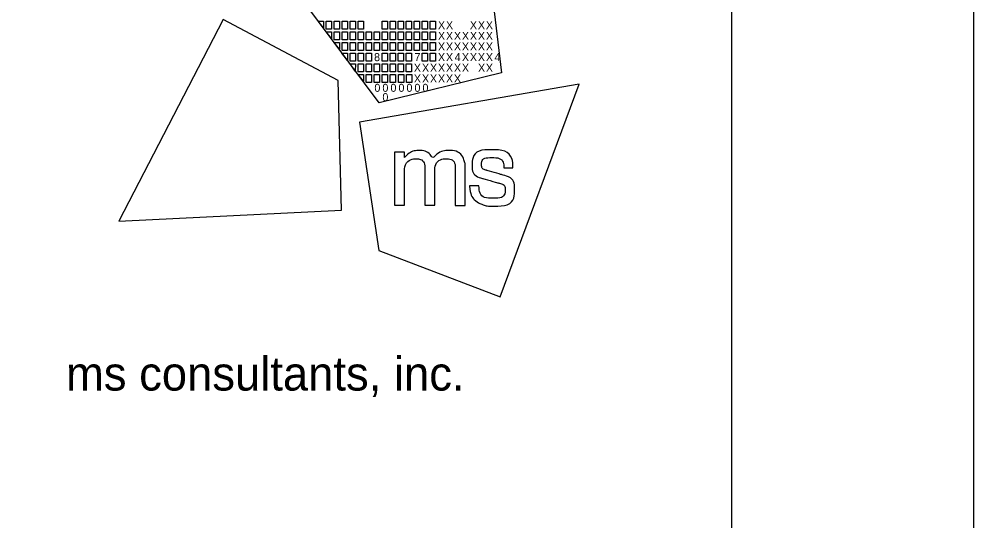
# Model space of a CAD drawing. Extents: x -18.6 to 78.7, y 0 to 36.9.
# Drawn here: x 32.03 to 34, y 2.68 to 3.716 of the extents above; entities that cross this region are included whole.
import ezdxf

# ---------------------------------------------------------------- set-up
doc = ezdxf.new("R2010")
doc.units = 0
for name, color, linetype in [('SH_Border', 7, 'Continuous'), ('SH_Cut_Line', 7, 'Continuous'), ('SH_Data', 7, 'Continuous')]:
    doc.layers.add(name, color=color, linetype=linetype)

msp = doc.modelspace()

# ---------------------------------------------------------------- linework, layer by layer
at = {"layer": 'SH_Border'}
for p, q in [((32.9688, 4.0861), (33.0253, 3.6052)), ((32.773, 3.543), (32.6175, 3.7519)), ((33.0253, 3.6052), (32.773, 3.543))]:
    msp.add_line(p, q, dxfattribs=at)
for points in [[(1.5, 21.5), (33.5, 21.5), (33.5, 0.5), (1.5, 0.5)], [(32.6471, 3.7117), (32.6581, 3.7117), (32.6581, 3.698)], [(32.6637, 3.7117), (32.6747, 3.7117), (32.6747, 3.6952), (32.6637, 3.6952)], [(32.6802, 3.7117), (32.6912, 3.7117), (32.6912, 3.6952), (32.6802, 3.6952)], [(32.6967, 3.7117), (32.7077, 3.7117), (32.7077, 3.6952), (32.6967, 3.6952)], [(32.7132, 3.7117), (32.7242, 3.7117), (32.7242, 3.6952), (32.7132, 3.6952)], [(32.7297, 3.7117), (32.7407, 3.7117), (32.7407, 3.6952), (32.7297, 3.6952)], [(32.7793, 3.7117), (32.7903, 3.7117), (32.7903, 3.6952), (32.7793, 3.6952)], [(32.7958, 3.7117), (32.8068, 3.7117), (32.8068, 3.6952), (32.7958, 3.6952)], [(32.8123, 3.7117), (32.8233, 3.7117), (32.8233, 3.6952), (32.8123, 3.6952)], [(32.8288, 3.7117), (32.8398, 3.7117), (32.8398, 3.6952), (32.8288, 3.6952)], [(32.8453, 3.7117), (32.8563, 3.7117), (32.8563, 3.6952), (32.8453, 3.6952)], [(32.8618, 3.7117), (32.8728, 3.7117), (32.8728, 3.6952), (32.8618, 3.6952)], [(32.8783, 3.7117), (32.8893, 3.7117), (32.8893, 3.6952), (32.8783, 3.6952)], [(32.6637, 3.6897), (32.6747, 3.6897), (32.6747, 3.676)], [(32.6747, 3.6897), (32.6747, 3.6897), (32.6747, 3.6897)], [(32.6802, 3.6897), (32.6912, 3.6897), (32.6912, 3.6732), (32.6802, 3.6732)], [(32.6967, 3.6897), (32.7077, 3.6897), (32.7077, 3.6732), (32.6967, 3.6732)], [(32.7132, 3.6897), (32.7242, 3.6897), (32.7242, 3.6732), (32.7132, 3.6732)], [(32.7297, 3.6897), (32.7407, 3.6897), (32.7407, 3.6732), (32.7297, 3.6732)], [(32.7462, 3.6897), (32.7572, 3.6897), (32.7572, 3.6732), (32.7462, 3.6732)], [(32.7627, 3.6897), (32.7737, 3.6897), (32.7737, 3.6732), (32.7627, 3.6732)], [(32.7793, 3.6897), (32.7903, 3.6897), (32.7903, 3.6732), (32.7793, 3.6732)], [(32.7958, 3.6897), (32.8068, 3.6897), (32.8068, 3.6732), (32.7958, 3.6732)], [(32.8123, 3.6897), (32.8233, 3.6897), (32.8233, 3.6732), (32.8123, 3.6732)], [(32.8288, 3.6897), (32.8398, 3.6897), (32.8398, 3.6732), (32.8288, 3.6732)], [(32.8453, 3.6897), (32.8563, 3.6897), (32.8563, 3.6732), (32.8453, 3.6732)], [(32.8618, 3.6897), (32.8728, 3.6897), (32.8728, 3.6732), (32.8618, 3.6732)], [(32.8783, 3.6897), (32.8893, 3.6897), (32.8893, 3.6732), (32.8783, 3.6732)], [(32.6802, 3.6677), (32.6912, 3.6677), (32.6912, 3.654)], [(32.6967, 3.6677), (32.7077, 3.6677), (32.7077, 3.6512), (32.6967, 3.6512)], [(32.7132, 3.6677), (32.7242, 3.6677), (32.7242, 3.6512), (32.7132, 3.6512)], [(32.7297, 3.6677), (32.7407, 3.6677), (32.7407, 3.6512), (32.7297, 3.6512)], [(32.7462, 3.6677), (32.7572, 3.6677), (32.7572, 3.6512), (32.7462, 3.6512)], [(32.7627, 3.6677), (32.7737, 3.6677), (32.7737, 3.6512), (32.7627, 3.6512)], [(32.7793, 3.6677), (32.7903, 3.6677), (32.7903, 3.6512), (32.7793, 3.6512)], [(32.7958, 3.6677), (32.8068, 3.6677), (32.8068, 3.6512), (32.7958, 3.6512)], [(32.8123, 3.6677), (32.8233, 3.6677), (32.8233, 3.6512), (32.8123, 3.6512)], [(32.8288, 3.6677), (32.8398, 3.6677), (32.8398, 3.6512), (32.8288, 3.6512)], [(32.8453, 3.6677), (32.8563, 3.6677), (32.8563, 3.6512), (32.8453, 3.6512)], [(32.8618, 3.6677), (32.8728, 3.6677), (32.8728, 3.6512), (32.8618, 3.6512)], [(32.8783, 3.6677), (32.8893, 3.6677), (32.8893, 3.6512), (32.8783, 3.6512)], [(32.7077, 3.6305), (32.6965, 3.6457), (32.7077, 3.6457)], [(32.7132, 3.6457), (32.7242, 3.6457), (32.7242, 3.6292), (32.7132, 3.6292)], [(32.7297, 3.6457), (32.7407, 3.6457), (32.7407, 3.6292), (32.7297, 3.6292)], [(32.7462, 3.6457), (32.7572, 3.6457), (32.7572, 3.6292), (32.7462, 3.6292)], [(32.7793, 3.6457), (32.7903, 3.6457), (32.7903, 3.6292), (32.7793, 3.6292)], [(32.7958, 3.6457), (32.8068, 3.6457), (32.8068, 3.6292), (32.7958, 3.6292)], [(32.8123, 3.6457), (32.8233, 3.6457), (32.8233, 3.6292), (32.8123, 3.6292)], [(32.8288, 3.6457), (32.8398, 3.6457), (32.8398, 3.6292), (32.8288, 3.6292)], [(32.8618, 3.6457), (32.8728, 3.6457), (32.8728, 3.6292), (32.8618, 3.6292)], [(32.8783, 3.6457), (32.8893, 3.6457), (32.8893, 3.6292), (32.8783, 3.6292)], [(32.724, 3.6082), (32.7132, 3.6237), (32.7242, 3.6237)], [(32.7297, 3.6237), (32.7407, 3.6237), (32.7407, 3.6072), (32.7297, 3.6072)], [(32.7462, 3.6237), (32.7572, 3.6237), (32.7572, 3.6072), (32.7462, 3.6072)], [(32.7627, 3.6237), (32.7737, 3.6237), (32.7737, 3.6072), (32.7627, 3.6072)], [(32.7793, 3.6237), (32.7903, 3.6237), (32.7903, 3.6072), (32.7793, 3.6072)], [(32.7958, 3.6237), (32.8068, 3.6237), (32.8068, 3.6072), (32.7958, 3.6072)], [(32.8123, 3.6237), (32.8233, 3.6237), (32.8233, 3.6072), (32.8123, 3.6072)], [(32.8288, 3.6237), (32.8398, 3.6237), (32.8398, 3.6072), (32.8288, 3.6072)], [(32.7302, 3.6017), (32.7407, 3.6017), (32.7408, 3.5875)], [(32.7463, 3.6017), (32.7573, 3.6017), (32.7573, 3.5852), (32.7463, 3.5852)], [(32.763, 3.6017), (32.774, 3.6017), (32.774, 3.5852), (32.763, 3.5852)], [(32.7794, 3.6017), (32.7904, 3.6017), (32.7904, 3.5852), (32.7794, 3.5852)], [(32.796, 3.6017), (32.807, 3.6017), (32.807, 3.5852), (32.796, 3.5852)], [(32.8129, 3.6017), (32.8239, 3.6017), (32.8239, 3.5851), (32.8129, 3.5851)], [(32.8296, 3.6017), (32.8406, 3.6017), (32.8406, 3.5851), (32.8296, 3.5851)]]:
    msp.add_lwpolyline(points, close=True, dxfattribs=at)
for points in [[(32.4512, 3.7149), (32.2359, 3.2988), (32.6956, 3.3215), (32.6884, 3.5892), (32.4512, 3.7149)], [(33.0229, 3.1422), (33.1859, 3.5814), (32.7324, 3.5029), (32.7722, 3.2381), (33.0229, 3.1422)]]:
    msp.add_lwpolyline(points, dxfattribs=at)
for points in [[(32.8048, 3.3315), (32.8048, 3.3315), (32.8048, 3.4409), (32.8048, 3.4409), (32.8048, 3.4409), (32.8255, 3.4409), (32.8255, 3.4409), (32.8255, 3.4409), (32.8255, 3.4297), (32.8255, 3.4297), (32.8346, 3.4399), (32.8457, 3.4445), (32.8555, 3.4445), (32.8688, 3.4445), (32.8791, 3.4372), (32.8837, 3.4266), (32.8915, 3.4381), (32.905, 3.4446), (32.9166, 3.4446), (32.9325, 3.4446), (32.9451, 3.435), (32.9494, 3.4213), (32.9494, 3.4212), (32.9494, 3.4212), (32.9494, 3.4212), (32.9501, 3.419), (32.9506, 3.4172), (32.9506, 3.4071), (32.9506, 3.4071), (32.9506, 3.3314), (32.9506, 3.3314), (32.9506, 3.3314), (32.9303, 3.3314), (32.9303, 3.3314), (32.9303, 3.3314), (32.9303, 3.4048), (32.9303, 3.4048), (32.9303, 3.4201), (32.9219, 3.4274), (32.911, 3.4274), (32.8995, 3.4274), (32.8879, 3.4171), (32.8879, 3.4001), (32.8879, 3.4001), (32.8879, 3.3315), (32.8879, 3.3315), (32.8879, 3.3315), (32.8674, 3.3315), (32.8674, 3.3315), (32.8674, 3.3315), (32.8674, 3.4059), (32.8674, 3.4059), (32.8674, 3.4203), (32.8588, 3.4274), (32.8496, 3.4274), (32.8384, 3.4274), (32.8254, 3.417), (32.8254, 3.3962), (32.8254, 3.3962), (32.8254, 3.3315), (32.8254, 3.3315), (32.8254, 3.3315), (32.8048, 3.3315), (32.8048, 3.3315)], [(32.9595, 3.3709), (32.9595, 3.3709), (32.9595, 3.3717), (32.9595, 3.3717), (32.9595, 3.3717), (32.9603, 3.3717), (32.9603, 3.3717), (32.9603, 3.3717), (32.9783, 3.3717), (32.9783, 3.3717), (32.9783, 3.3717), (32.9789, 3.3717), (32.9789, 3.3717), (32.9789, 3.3717), (32.979, 3.371), (32.979, 3.371), (32.9803, 3.3554), (32.9887, 3.346), (33.009, 3.346), (33.0273, 3.346), (33.0333, 3.3554), (33.0333, 3.3631), (33.0333, 3.3732), (33.0256, 3.3758), (33.0175, 3.378), (33.0175, 3.378), (32.987, 3.3867), (32.987, 3.3867), (32.972, 3.3909), (32.9648, 3.4019), (32.9648, 3.4142), (32.9648, 3.4303), (32.9768, 3.4462), (33.0052, 3.4462), (33.0348, 3.4462), (33.0489, 3.4285), (33.0489, 3.4095), (33.0489, 3.4095), (33.0489, 3.4087), (33.0489, 3.4087), (33.0489, 3.4087), (33.0482, 3.4087), (33.0482, 3.4087), (33.0482, 3.4087), (33.0312, 3.4087), (33.0312, 3.4087), (33.0312, 3.4087), (33.0305, 3.4087), (33.0305, 3.4087), (33.0305, 3.4087), (33.0305, 3.4094), (33.0305, 3.4094), (33.0301, 3.4208), (33.0226, 3.43), (33.0056, 3.43), (32.9891, 3.43), (32.9843, 3.4218), (32.9843, 3.4157), (32.9843, 3.4108), (32.9869, 3.4059), (32.9959, 3.4033), (32.9959, 3.4033), (33.0255, 3.3948), (33.0255, 3.3948), (33.0462, 3.3889), (33.0527, 3.3777), (33.0527, 3.3639), (33.0527, 3.3462), (33.041, 3.3298), (33.0087, 3.3298), (32.9952, 3.3298), (32.9877, 3.3321), (32.9823, 3.3348), (32.969, 3.3414), (32.9609, 3.3536), (32.9595, 3.3709)]]:
    msp.add_open_spline(points, degree=3, dxfattribs=at)
at = {"layer": 'SH_Cut_Line'}
msp.add_lwpolyline([(0, 0), (34, 0), (34, 22), (0, 22)], close=True, dxfattribs=at)
at = {"layer": 'SH_Data'}
msp.add_line((32.75, 3.5), (32.75, 3.5), dxfattribs=at)

# ---------------------------------------------------------------- texts
at = {"layer": 'SH_Border'}
for s, height, p in [('X', 0.0165, (32.8945, 3.6952)), ('X', 0.0165, (32.911, 3.6952)), ('X', 0.0165, (32.9604, 3.6952)), ('X', 0.0165, (32.9769, 3.6952)), ('X', 0.0165, (32.9933, 3.6952)), ('X', 0.0165, (32.8945, 3.6732)), ('X', 0.0165, (32.911, 3.6732)), ('X', 0.0165, (32.9274, 3.6732)), ('X', 0.0165, (32.9439, 3.6732)), ('X', 0.0165, (32.9604, 3.6732)), ('X', 0.0165, (32.9769, 3.6732)), ('X', 0.0165, (32.9933, 3.6732)), ('X', 0.0165, (32.8945, 3.6512)), ('X', 0.0165, (32.911, 3.6512)), ('X', 0.0165, (32.9274, 3.6512)), ('X', 0.0165, (32.9439, 3.6512)), ('X', 0.0165, (32.9604, 3.6512)), ('X', 0.0165, (32.9769, 3.6512)), ('X', 0.0165, (32.9933, 3.6512)), ('8', 0.0165, (32.7627, 3.6292)), ('7', 0.0165, (32.846, 3.6292)), ('X', 0.0165, (32.8945, 3.6292)), ('X', 0.0165, (32.911, 3.6292)), ('4', 0.0165, (32.9288, 3.6292)), ('X', 0.0165, (32.9439, 3.6292)), ('X', 0.0165, (32.9604, 3.6292)), ('X', 0.0165, (32.9769, 3.6292)), ('X', 0.0165, (32.9933, 3.6292)), ('4', 0.0165, (33.0111, 3.6292)), ('X', 0.0165, (32.8447, 3.6072)), ('X', 0.0165, (32.8616, 3.6072)), ('X', 0.0165, (32.878, 3.6072)), ('X', 0.0165, (32.8945, 3.6072)), ('X', 0.0165, (32.911, 3.6072)), ('X', 0.0165, (32.9274, 3.6072)), ('X', 0.0165, (32.9439, 3.6072)), ('X', 0.0165, (32.9771, 3.6072)), ('X', 0.0165, (32.9933, 3.6072)), ('X', 0.0165, (32.8447, 3.5851)), ('X', 0.0165, (32.8616, 3.5851)), ('X', 0.0165, (32.878, 3.5851)), ('X', 0.0165, (32.8945, 3.5851)), ('X', 0.0165, (32.911, 3.5851)), ('X', 0.0165, (32.9274, 3.5851)), ('0', 0.0165, (32.7634, 3.5659)), ('0', 0.0165, (32.7799, 3.5659)), ('0', 0.0165, (32.7965, 3.5659)), ('0', 0.0165, (32.813, 3.5659)), ('0', 0.0165, (32.8295, 3.5659)), ('0', 0.0165, (32.846, 3.5659)), ('0', 0.0165, (32.8625, 3.5659)), ('0', 0.0165, (32.7799, 3.5467)), ('ms consultants, inc.', 0.07, (32.1273, 2.9489))]:
    msp.add_text(s, height=height, rotation=360, dxfattribs=at).set_placement(p)

doc.saveas('drawing.dxf')
